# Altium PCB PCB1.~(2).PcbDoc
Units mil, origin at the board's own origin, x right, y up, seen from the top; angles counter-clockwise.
Board outline 625.03 x 435.03 mil, 2 copper layers (Top Layer, Bottom Layer); 3 components, 3 nets, 6 pads, 0 vias.
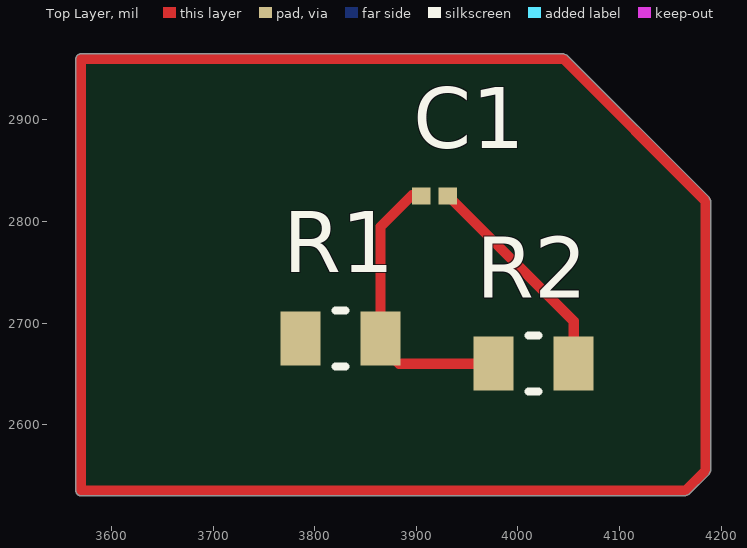
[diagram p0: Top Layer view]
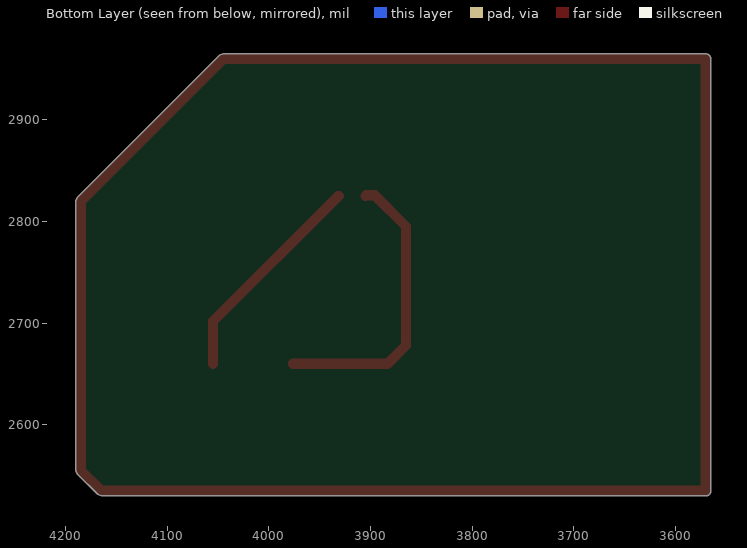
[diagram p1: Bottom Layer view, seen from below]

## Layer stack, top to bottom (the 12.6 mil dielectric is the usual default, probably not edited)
Top Solder: solder mask 0.4, Solder Resist, Dk 3.5
Top Layer: signal copper 1.4
Dielectric 1: dielectric 12.6, FR-4, Dk 4.8
Bottom Layer: signal copper 1.4
Bottom Solder: solder mask 0.4, Solder Resist, Dk 3.5

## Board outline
3564.99,2535 ccw(c3570,2535) 3570,2529.99 4165,2529.99 4168.55,2531.45 4188.55,2551.45 4190.02,2555 4190.02,2820 4188.55,2823.55 4048.55,2963.55 4045,2965.01 3570,2965.01 ccw(c3570,2960) 3564.99,2960

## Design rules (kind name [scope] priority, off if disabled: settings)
Clearance [All] p1: gap=10 ignorepadtopadclearanceinfootprint=FALSE except(0: Arc-Hole Track-Hole SMDPad-Hole THPad-Hole Via-Hole Fill-Hole Poly-Hole Region-Hole Text-Hole)
PolygonConnect [All] p1: connectstyle=Relief reliefconductorwidth=10 reliefentries=4 polygonreliefangle="90 Angle" airgapwidth=10
RoutingVias [All] p1: holewidth=28 width=50 viastyle="Through Hole" minholewidth=28 minwidth=50 maxholewidth=28 maxwidth=50
SolderMaskExpansion [All] p1: expansion=4 istentingtop=FALSE
Width [All] p1: maxlimit=10 minlimit=10 preferedwidth=10
30 further rules are at their usual default settings.

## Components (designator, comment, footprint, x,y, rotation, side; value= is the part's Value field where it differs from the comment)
C1 "MC000315" CAPC0603X33X15NL03T05 3917.99,2825 r0 top
R1 "RN73C2A10K7BTG" FP-RN732A-MFG 3825.63,2685 r0 top value=10.7KΩ
R2 "RN73C2A10K7BTG" FP-RN732A-MFG 4015.63,2660 r0 top value=10.7KΩ

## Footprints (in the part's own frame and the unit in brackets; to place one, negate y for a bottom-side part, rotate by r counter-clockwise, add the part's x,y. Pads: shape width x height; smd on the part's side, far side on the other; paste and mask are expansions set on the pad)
CAPC0603X33X15NL03T05 [mm] "Chip Capacitor, 2-Leads, Body 0.60x0.30mm, IPC Medium Density"
  rect 0.46x0.42 smd: 1(-0.33,0) 2(0.33,0)
  body extent -0.31,-0.17 0.32,0.16, height 0.33
FP-RN732A-MFG [mm]
  rect 1x1.35 smd paste+0 mask+0: 1(-1,0) 2(1,0)
  silkscreen extent -0.13,-0.7 0.13,0.7, body extent -1.6,-0.8 1.6,0.8, height 0.25

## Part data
C1: library part CMP-2010-01738-1, Manufacturer=Multicomp
R1 R2: library part CMP-03211-011054-1, "SMD Chip Resistor, Thin Film, 10.7KΩ, 100 V, 0805 [2012 Metric], 100 mW, 0.1%, RN73 Series", Manufacturer="TE Connectivity", Package=RN732A, Power Rating=0.1W, Resistance=10.7KΩ, Temperature="-55°C to 155°C", Temperature Coefficient=10ppm/°C, Temperature Range High=155°C, Temperature Range Low=-55°C, Tolerance=0.1%, Voltage Rating=100V

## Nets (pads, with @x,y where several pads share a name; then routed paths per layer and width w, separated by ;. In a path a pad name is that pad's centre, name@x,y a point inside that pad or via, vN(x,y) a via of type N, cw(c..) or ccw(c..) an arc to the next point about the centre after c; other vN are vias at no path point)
GND: C1.2 R2.2 | length 216.8
  Top Layer w10: C1.2 3931.77,2825 4055,2701.77 R2.2
NetC1_1: C1.1 R1.2 R2.1 | length 288.8
  Top Layer w10: C1.1 3904.14,2825.86 3895.86,2825.86 3865,2795 R1.2 3865,2678.11 3883.11,2660 R2.1
VCC: R1.1
copper on no net: | length 2456.3
  Top Layer w10: 3575,2960 4045,2960 ; 4045,2960 3570,2960 3570,2535 4165,2535 4185,2555 4185,2820 4045,2960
